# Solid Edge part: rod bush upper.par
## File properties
Author: Deepak Maini
Template: Normal.par
Last saved by: Robert a Rhodes jr
Revision: 2
Application: Solid Edge
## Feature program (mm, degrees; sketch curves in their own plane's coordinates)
sketch for "unnamed Protrusion 1" #1 plane through (0, 0, 0) normal (0, 0, 1) x-axis (1, 0, 0)
  circle centre (0, 0) radius 11
sketch for "unnamed Protrusion 1" #2 plane through (0, 0, 0) normal (0, 0, 1) x-axis (1, 0, 0)
  circle centre (0, 0) radius 12
extrude "unnamed Protrusion 1" add finite 42 along -normal
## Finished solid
Body 1: solid body, 4 faces, 4 edges, 0 vertices.
  Faces by surface: cylinder 2, plane 2
  Edges by curve: circle 4
Bounding box of the edges (mm): 24.000 x 24.000 x 42.000, from (-12, -12, -42) to (12, 12, 0).
Cylindrical faces by radius (mm): R11 x1, R12 x1
Planar faces by outward normal: +z 1, -z 1
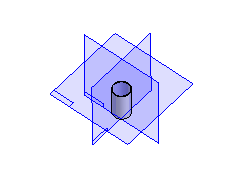
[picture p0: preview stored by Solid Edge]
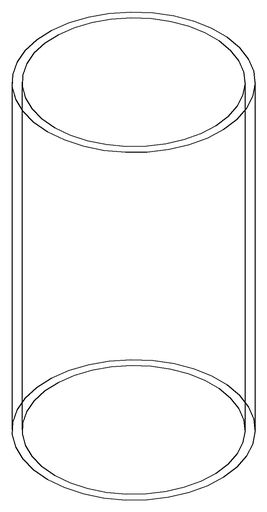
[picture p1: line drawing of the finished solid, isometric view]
